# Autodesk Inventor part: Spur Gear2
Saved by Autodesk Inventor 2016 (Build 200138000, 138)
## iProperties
Created: 2015-08
Part Number: Spur Gear2
Material: Steel
Document SubType Name: Modeling
Designer: Ugljesa
Categories: <?xml version="1.0" encoding="UTF-16"?> <MemberInstance><Categories><FamilyTemplate><FamilyTemplateParameter ValueType="xs:double" Id="1" ObjectReferenceKey="da
Mass: 203.429 g
Surface Area: 109.446 cm^2
Volume: 25.9145 cm^3
Density: 7.85 g/cm^3
Appearance: Steel
CustomPartVersion: 1
Author: Ugljesa
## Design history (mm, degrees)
sketch "Sketch1"
  geometry: C1 r 27.719 at (0, 0)
  constraints: 1 centre point
  dimensions: "d0" = 55.43862 diameter of C1 (= da_da)
extrude "Extrusion1" new body sketch "Sketch1" distance "d1" = 20 (= da_b); taper "d2" = 0 deg
workplane "Work Plane2"
sketch "Sketch2"
  geometry: C1 r 27.719 at (0, 0) reference; C2 r 25.143 at (0, 0)
  constraints: 1 centre point, 1 coincident
  dimensions: "d3" = 50.28571 diameter of C2 (= da_dw)
feature "Pitch Diameter" sketch "Sketch2" dims "d4" = 10, "d5" = 0
workplane "Work Plane8"
workplane "Work Plane9"
feature "Spur Gear" dims "da_b" = 20, "da_d" = 49.98646, "da_aw" = 80, "da_da" = 55.43862, "da_df" = 45.3343, "da_dw" = 50.28571, angle "da_beta" = 8 deg, "da_lefttooth" = 0, "da_righttooth" = 10
node "Keyway1"
body "Solid1"
body "Srf1"
feature "Hub Keyway"
other parameters: "d17" = 0, "d34" = 1.428 (computed from da_z), "d39" = 0, "d41" = 0, "d47" = 0, "d48" = 0
